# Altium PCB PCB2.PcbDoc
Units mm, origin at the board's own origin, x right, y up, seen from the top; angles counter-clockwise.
Board outline 51.56 x 61.72 mm, 2 copper layers (Top Layer, Bottom Layer); 23 components, 19 nets, 92 pads, 7 vias.
Unrouted connection lines stored in the file: 1.
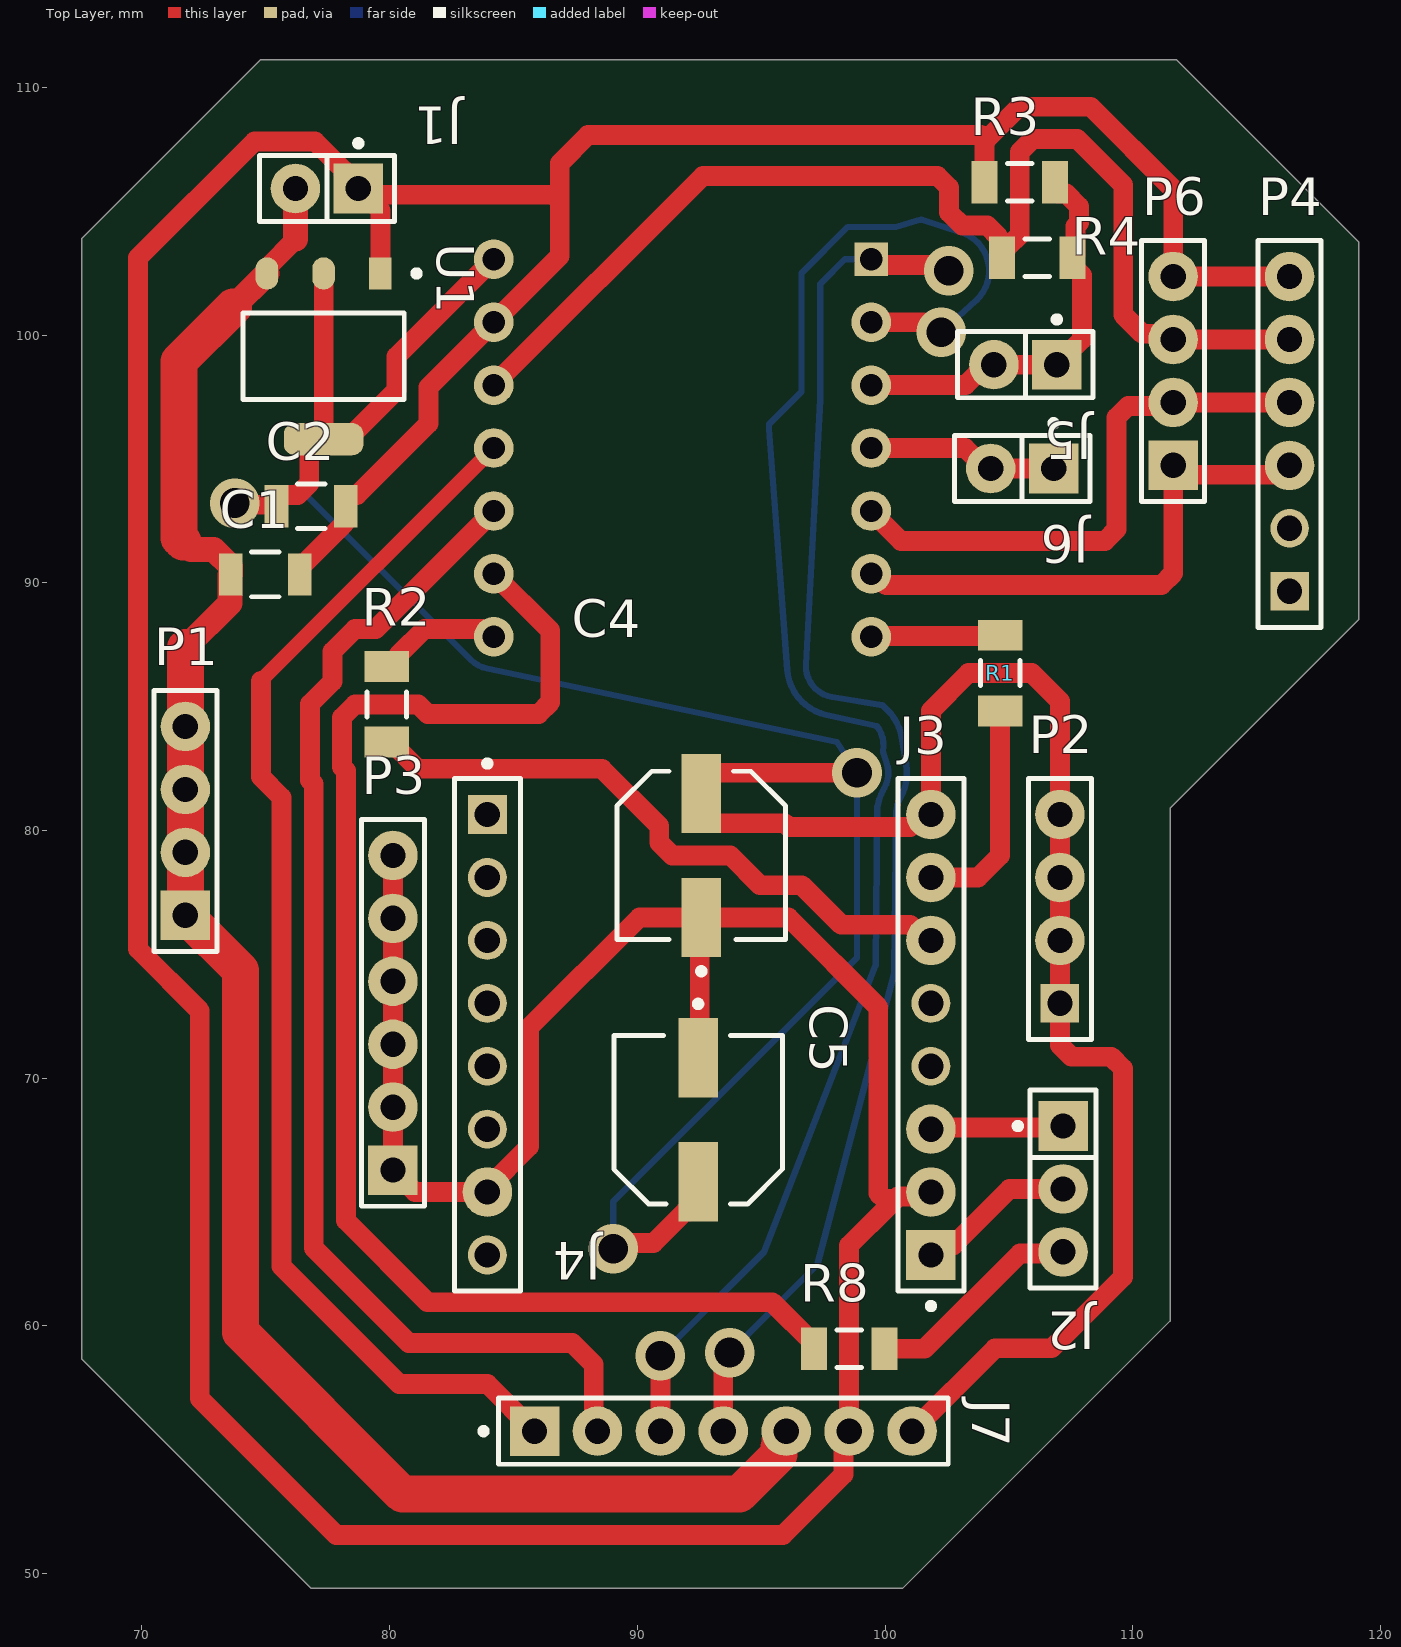
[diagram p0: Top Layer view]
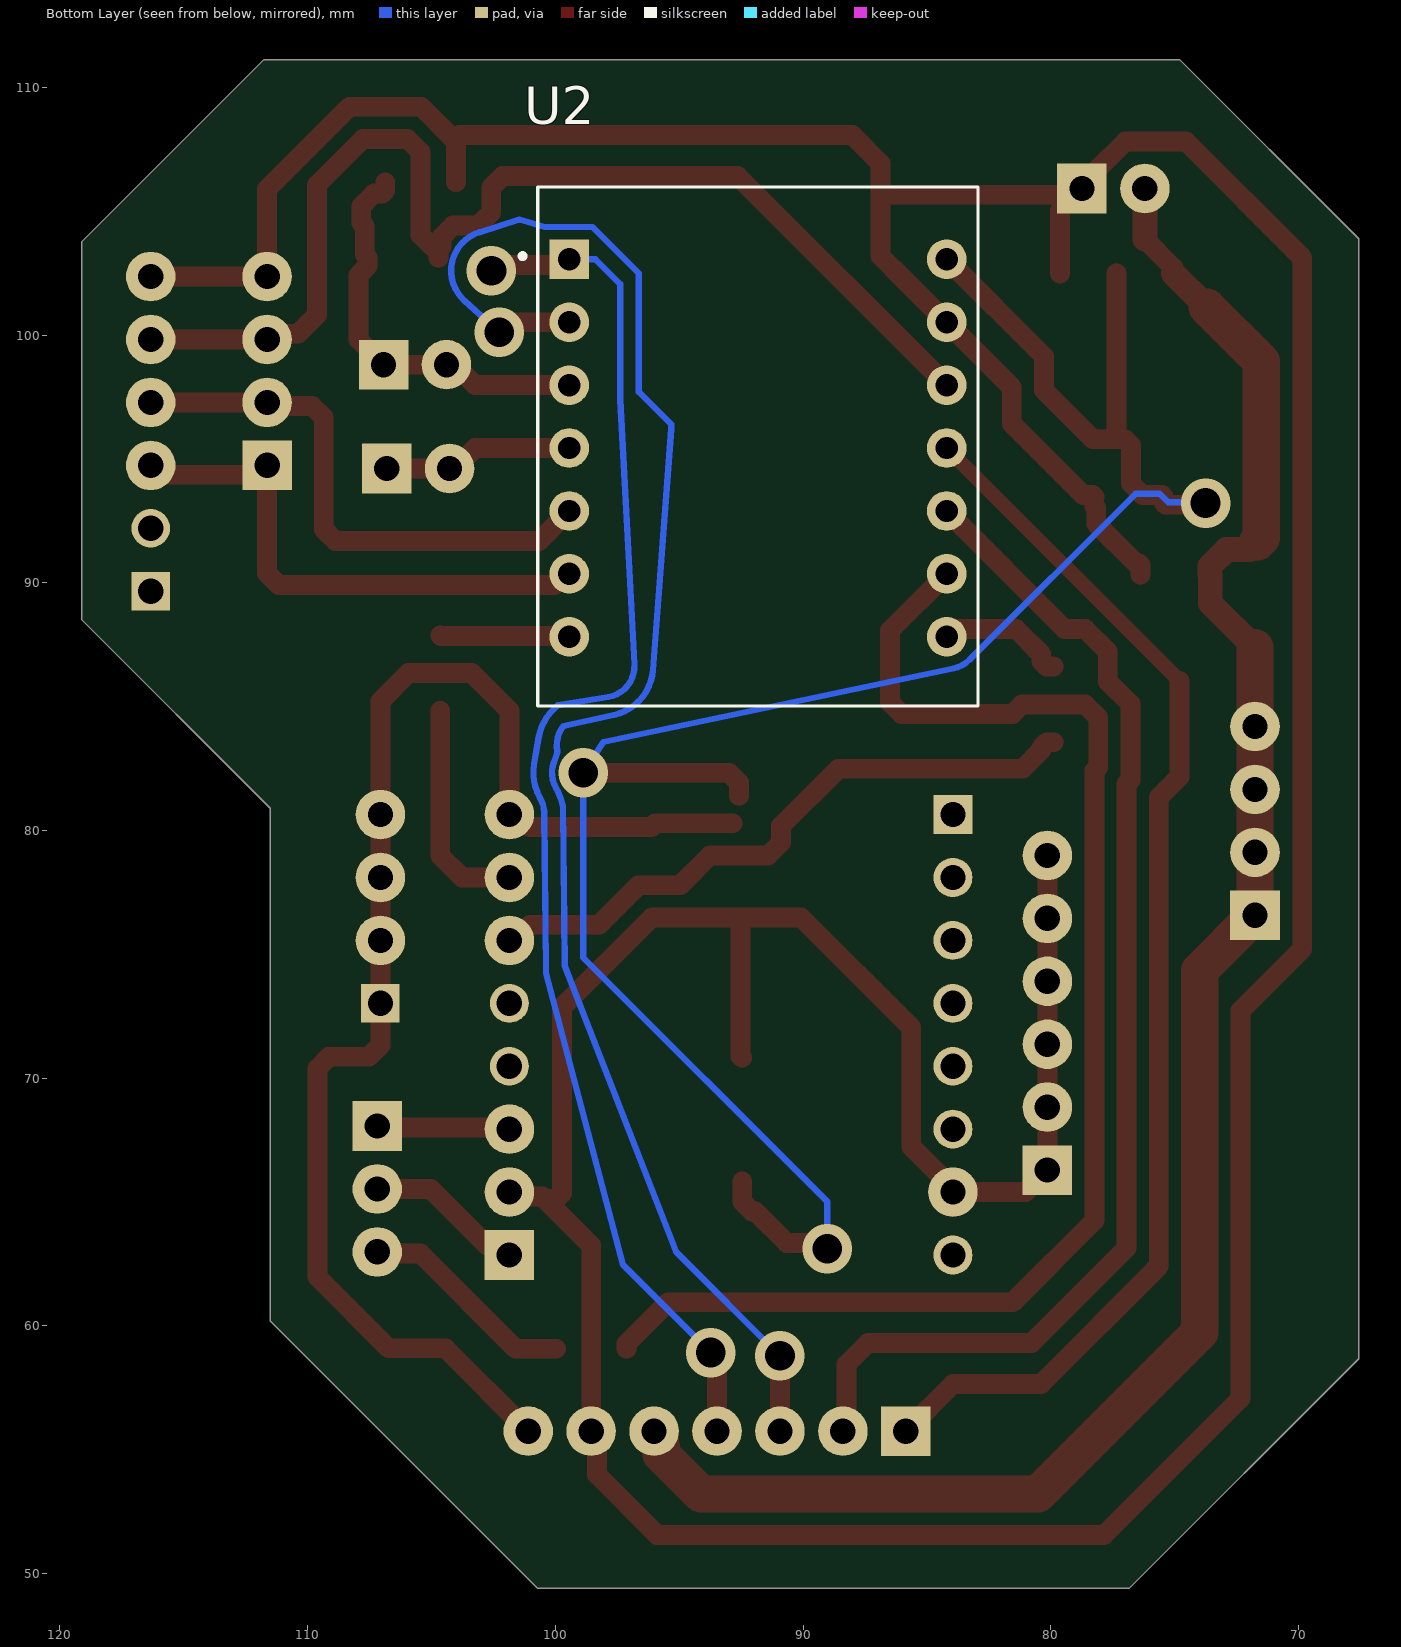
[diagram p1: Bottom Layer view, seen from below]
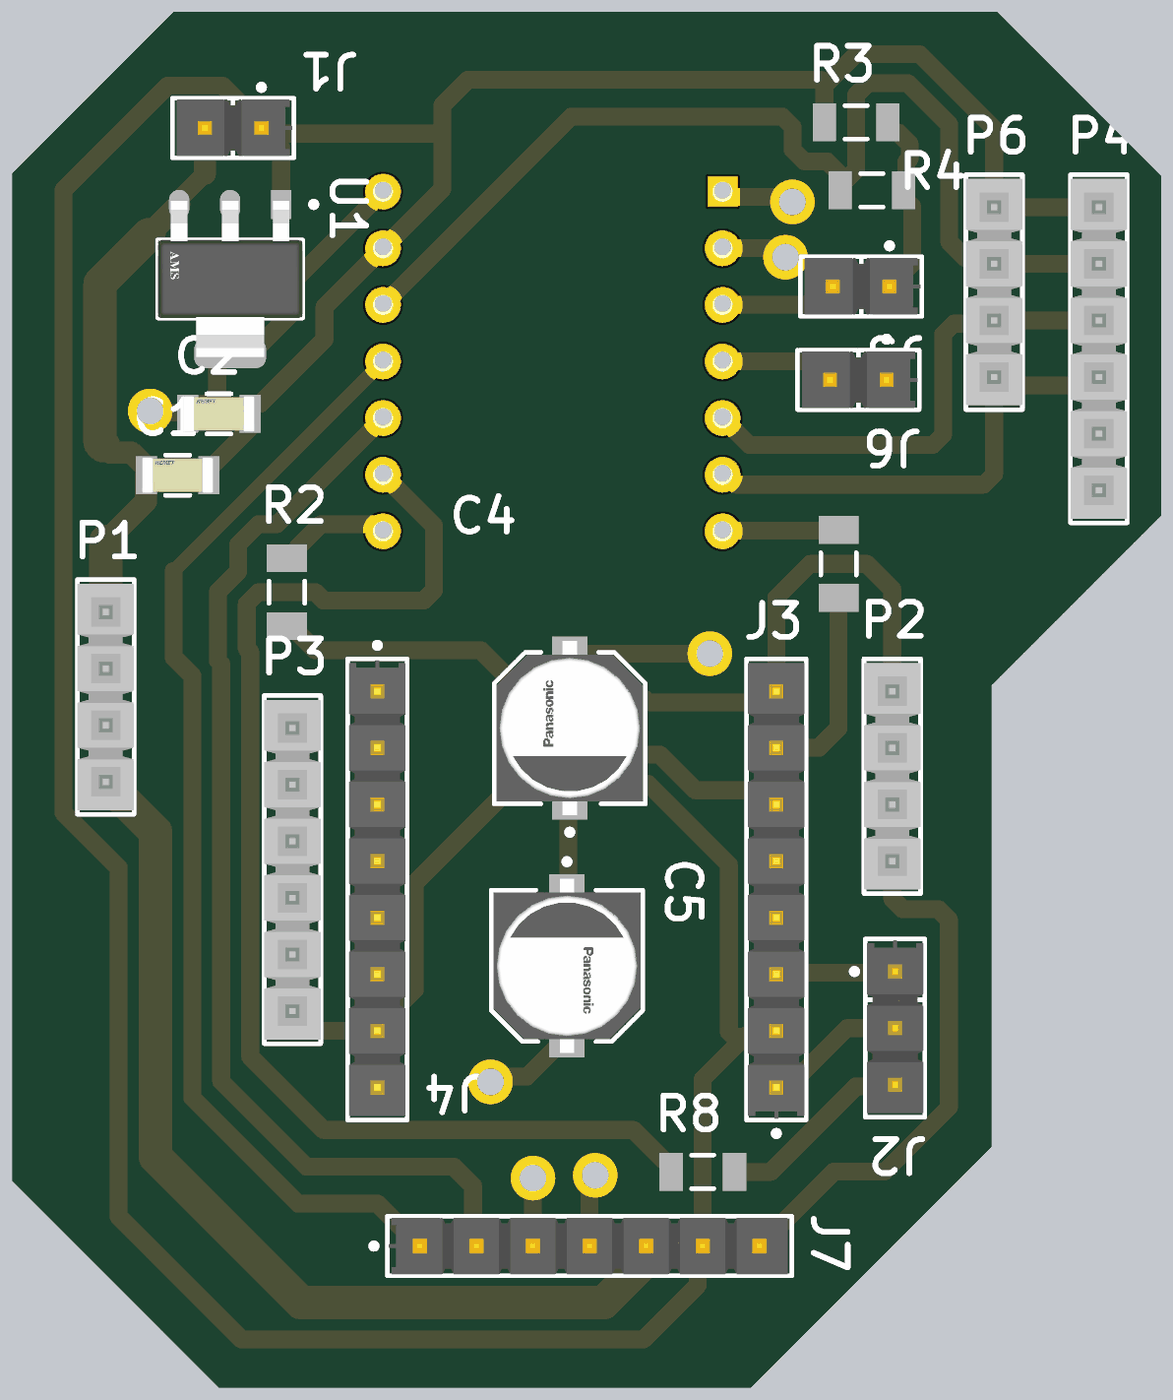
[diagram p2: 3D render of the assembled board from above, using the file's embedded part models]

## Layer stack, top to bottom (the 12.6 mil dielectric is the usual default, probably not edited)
Top Solder: solder mask 0.0102, Solder Resist, Dk 3.5
Top Layer: signal copper 0.0356
Dielectric 1: dielectric 0.32, FR-4, Dk 4.8
Bottom Layer: signal copper 0.0356
Bottom Solder: solder mask 0.0102, Solder Resist, Dk 3.5

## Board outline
67.564,58.674 76.835,49.403 100.711,49.403 111.506,60.198 111.506,80.899 119.126,88.519 119.126,103.759 111.76,111.125 74.803,111.125 67.564,103.886

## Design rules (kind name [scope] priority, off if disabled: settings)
Clearance [All] p1: gap=0.5 ignorepadtopadclearanceinfootprint=FALSE
PolygonConnect [All] p1: connectstyle=Relief reliefconductorwidth=0.254 reliefentries=4 polygonreliefangle="90 Angle" airgapwidth=0.254
RoutingVias [All] p1: holewidth=0.711 width=1.27 viastyle="Through Hole" minholewidth=0.711 minwidth=1.27 maxholewidth=0.711 maxwidth=1.27
SolderMaskExpansion [All] p1: expansion=0 istentingtop=FALSE
SupplyNets "Schematic Supply Nets_3" [InNet('+9')] p1: voltage=0.000
SupplyNets "Schematic Supply Nets_2" [InNet('GND')] p2: voltage=0.000
SupplyNets "Schematic Supply Nets_1" [InNet('+3.3')] p3: voltage=0.000
SupplyNets "Schematic Supply Nets" [InNet('VCC3.3')] p4: voltage=0.000
Width [All] p1: maxlimit=1.6 minlimit=0.254 preferedwidth=0.8 toplayer_minwidth=0.6 bottomlayer_maxwidth=0.254 bottomlayer_prefwidth=0.254 minimp=50.000000 maximp=50.000000 favimp=50.000000
30 further rules are at their usual default settings.

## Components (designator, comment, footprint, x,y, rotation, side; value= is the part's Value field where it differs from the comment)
C1 "C1206C153K5RAC" FP-C1206C-EB-MFG 74.983,90.338 r0 top value="15,000 pF"
C2 "C1206C153K5RAC" FP-C1206C-EB-MFG 76.835,93.091 r0 top value="15,000 pF"
C4 "EEEFPC221XAP" FP-FPD8-MFG 92.583,78.994 r90 top
C5 "EEEFPC221XAP" FP-FPD8-MFG 92.456,68.326 r270 top
J1 "BATERIA" FP-TSW-102-14-G-S-MFG 77.47,105.918 r180 top
J2 "TSW-103-14-G-S" FP-TSW-103-14-G-S-MFG 107.188,65.532 r270 top
J3 "TSW-108-08-G-S" FP-TSW-108-08-G-S-MFG#1 101.854,71.755 r90 top
J4 "TSW-108-08-G-S" FP-TSW-108-08-G-S-MFG#2 83.947,71.755 r270 top
J5 "TSW-102-14-G-S" FP-TSW-102-14-G-S-MFG 105.664,98.806 r180 top
J6 "TSW-102-14-G-S" FP-TSW-102-14-G-S-MFG 105.537,94.615 r180 top
J7 "TSW-107-07-G-S" FP-TSW-107-07-G-S-MFG 93.472,55.753 r0 top
P1 "TSW-104-08-G-S" SMTC-TSW-104-08-X-S#1 71.755,76.581 r90 top
P2 "TSW-104-08-G-S" SMTC-TSW-104-08-X-S#2 107.061,73.025 r90 top
P3 "TSW-106-17-L-S-LL" SMTC-TSW-106-17-X-S-LL#1 80.137,66.294 r90 top
P4 "TSW-106-17-L-S-LL" SMTC-TSW-106-17-X-S-LL#2 116.332,89.662 r90 top
P6 "TSW-104-08-G-S" SMTC-TSW-104-08-X-S#1 111.633,94.742 r90 top
R1 "RC1206FR-10750RL" RESC3116X65X40ML10T20 104.648,86.359 r270 top
R2 "RC1206FR-10750RL" RESC3116X65X40ML10T20 79.883,85.091 r270 top
R3 "RC1206FR-076R98L" RESC3116X65X40NL10T20 105.438,106.172 r0 top
R4 "RC1206FR-076R98L" RESC3116X65X40NL10T20 106.144,103.124 r0 top
R8 "RC1206FR-076R98L" RESC3116X65X40NL10T20 98.552,59.079 r0 top
U1 "ams1117" FP-ams1117-IPC_B 77.339,99.144 r270 top
U2 "XIAO_ESP32C3" MODULE_XIAO_ESP32C3 91.821,95.504 r180 bottom

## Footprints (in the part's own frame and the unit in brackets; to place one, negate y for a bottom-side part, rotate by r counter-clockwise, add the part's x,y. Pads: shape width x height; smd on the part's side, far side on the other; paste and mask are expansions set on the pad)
FP-ams1117-IPC_B [mm]
  rect 1.304x0.912 smd paste+0 mask+0: 1(-3.345,2.29)
  rrect100% 1.304x0.912 smd paste+0 mask+0: 2(-3.345,0) 3(-3.345,-2.29)
  rrect70% 1.304x3.222 smd paste+0 mask+0: 4(3.345,0)
  silkscreen extent -3.47,-3.25 1.75,3.88, body extent -4.25,-3.5 4.25,3.5, height 0.25
FP-C1206C-EB-MFG [mm]
  rect 0.95x1.7 smd paste+0 mask+0: 1(-1.4,0) 2(1.4,0)
  silkscreen extent -0.55,-0.9 0.55,0.9, body extent -2,-1 2,1, height 0.25
FP-FPD8-MFG [mm]
  rect 3.2x1.6 smd paste+0 mask+0: 1(-2.5,0) 2(2.5,0)
  silkscreen extent -4.8,-3.4 3.4,3.4, body extent -4.35,-3.65 4.35,3.65, height 0.25
FP-TSW-102-14-G-S-MFG [mm]
  rect 2x2 hole 1.02 paste-2539.97 mask+0: 1(-1.27,0)
  round 2 hole 1.02 paste-2539.97 mask+0: 2(1.27,0)
  silkscreen extent -2.73,-1.95 2.73,1.34, body extent -2.83,-1.44 2.83,1.44, height 0.25
FP-TSW-103-14-G-S-MFG [mm]
  rect 2x2 hole 1.02 paste-2539.97 mask+0: 1(-2.54,0)
  round 2 hole 1.02 paste-2539.97 mask+0: 2(0,0) 3(2.54,0)
  silkscreen extent -4,-1.95 4,1.34, body extent -4.1,-1.44 4.1,1.44, height 0.25
FP-TSW-107-07-G-S-MFG [mm]
  rect 2x2 hole 1.02 paste-2539.97 mask+0: 1(-7.62,0)
  round 2 hole 1.02 paste-2539.97 mask+0: 2(-5.08,0) 3(-2.54,0) 4(0,0) 5(2.54,0) 6(5.08,0) 7(7.62,0)
  silkscreen extent -9.8,-1.34 9.08,1.34, body extent -9.18,-1.44 9.18,1.44, height 0.25
FP-TSW-108-08-G-S-MFG#1 [mm]
  rect 2x2 hole 1.02 paste-2539.97 mask+0: 1(-8.89,0)
  round 2 hole 1.02 paste-2539.97 mask+0: 2(-6.35,0) 3(-3.81,0) 6(3.81,0) 7(6.35,0) 8(8.89,0)
  round 1.57 hole 1.02 paste-2539.97 mask+0: 4(-1.27,0) 5(1.27,0)
  silkscreen extent -11.07,-1.34 10.35,1.34, body extent -10.45,-1.44 10.45,1.44, height 0.25
FP-TSW-108-08-G-S-MFG#2 [mm]
  rect 1.57x1.57 hole 1.02 paste-2539.97 mask+0: 1(-8.89,0)
  round 1.57 hole 1.02 paste-2539.97 mask+0: 2(-6.35,0) 3(-3.81,0) 4(-1.27,0) 5(1.27,0) 6(3.81,0) 8(8.89,0)
  round 2 hole 1.02 paste-2539.97 mask+0: 7(6.35,0)
  silkscreen extent -11.07,-1.34 10.35,1.34, body extent -10.45,-1.44 10.45,1.44, height 0.25
MODULE_XIAO_ESP32C3 [mm]
  rect 1.6x1.6 / inner round 1.358 / far side rect 1.358x1.358 hole 0.9 mask+0.102: 1(-7.62,7.557)
  round 1.6 hole 0.9 mask+0.102: 2(-7.62,5.017) 3(-7.62,2.477) 4(-7.62,-0.063) 5(-7.62,-2.603) 6(-7.62,-5.143) 7(-7.62,-7.683) 8(7.62,-7.684) 9(7.62,-5.144) 10(7.62,-2.604) 11(7.62,-0.064) 12(7.62,2.476) 13(7.62,5.016) 14(7.62,7.556)
  silkscreen extent -9.6,-10.48 8.89,10.48, body extent -8.89,-10.48 8.89,11.99, height 4.21
RESC3116X65X40ML10T20 [mm] "Chip Resistor, 2-Leads, Body 3.10x1.60mm, IPC Low Density"
  rect 1.25x1.8 smd: 1(-1.525,0) 2(1.525,0)
  silkscreen extent -0.5,-0.8 0.5,0.8, body extent -1.6,-0.85 1.6,0.85, height 0.65
RESC3116X65X40NL10T20 [mm] "Chip Resistor, 2-Leads, Body 3.10x1.60mm, IPC Medium Density"
  rect 1.05x1.7 smd: 1(-1.425,0) 2(1.425,0)
  silkscreen extent -0.5,-0.75 0.5,0.75, body extent -1.6,-0.85 1.6,0.85, height 0.65
SMTC-TSW-104-08-X-S#1 [mm] ".025 SQ Post Terminal Strip Assembly, 1x4 Pins, Vertical, 2.54mm Pitch, Male"
  rect 2x2 hole 1.02: 1(0,0)
  round 2 hole 1.02: 2(2.54,0) 3(5.08,0) 4(7.62,0)
  silkscreen extent -1.46,-1.27 9.08,1.27, body extent -1.27,-1.27 8.89,1.27, height 8.38
SMTC-TSW-104-08-X-S#2 [mm] ".025 SQ Post Terminal Strip Assembly, 1x4 Pins, Vertical, 2.54mm Pitch, Male"
  rect 1.55x1.55 hole 1.02: 1(0,0)
  round 2 hole 1.02: 2(2.54,0) 3(5.08,0) 4(7.62,0)
  silkscreen extent -1.46,-1.27 9.08,1.27, body extent -1.27,-1.27 8.89,1.27, height 8.38
SMTC-TSW-106-17-X-S-LL#1 [mm] ".025 SQ Post Terminal Strip Assembly, 1x6 Pins, Vertical, 2.54mm Pitch, Male"
  rect 2x2 hole 1.02: 1(0,0)
  round 2 hole 1.02: 2(2.54,0) 3(5.08,0) 4(7.62,0) 5(10.16,0) 6(12.7,0)
  silkscreen extent -1.46,-1.27 14.16,1.27, body extent -1.27,-1.27 13.97,1.27, height 18.29
SMTC-TSW-106-17-X-S-LL#2 [mm] ".025 SQ Post Terminal Strip Assembly, 1x6 Pins, Vertical, 2.54mm Pitch, Male"
  rect 1.55x1.55 hole 1.02: 1(0,0)
  round 1.55 hole 1.02: 2(2.54,0)
  round 2 hole 1.02: 3(5.08,0) 4(7.62,0) 5(10.16,0) 6(12.7,0)
  silkscreen extent -1.46,-1.27 14.16,1.27, body extent -1.27,-1.27 13.97,1.27, height 18.29

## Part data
C1 C2: library part CMP-03020-027494-1, "C1206 15,000 pF X7R 10.00% 50 V", Capacitance="15,000 pF", Manufacturer=KEMET, Package=C1206C-EB, Temperature="-55°C to +150°C", Temperature Characteristic=X7R, Temperature Coefficient=15%, Temperature Range High=+150°C, Temperature Range Low=-55°C, Tolerance=0.1, Voltage Rating="50 V"
C4 C5: library part CMP-05427-002138-1, "CAP ALUM 220UF 20% 16V SMD", Capacitance=220uF, Case/Package=SMD/SMT, ESR (Equivalent Series Resistance)=160mR, Leakage Current=35.2uA, Max Operating Temperature=105°C, Min Operating Temperature=-55°C, Package Quantity=900, Ripple Current=600mA, Tolerance=20%, Voltage=16V
J1 J5 J6: library part CMP-02766-001740-1, "CONN HEADER VERT 2POS 2.54MM", Color=Black, Flammability Rating="UL94 V-0", Max Current Rating=7.6A, Max Operating Temperature=125°C, Max Voltage Rating (AC)=550V, Min Operating Temperature=-55°C, Package Quantity=1
J2: library part CMP-02766-001743-1, "CONN HEADER VERT 3POS 2.54MM", Color=Black, Flammability Rating="UL94 V-0", Max Current Rating=7.6A, Max Operating Temperature=125°C, Max Voltage Rating (AC)=550V, Min Operating Temperature=-55°C, Package Quantity=1
J3 J4: library part CMP-02766-000001-1, "CONN HEADER VERT 8POS 2.54MM", Manufacturer=Samtec, Temperature="-55°C to +125°C", Temperature Range High=+125°C, Temperature Range Low=-55°C
J7: library part CMP-02766-000065-1, "CONN HEADER VERT 7POS 2.54MM", Manufacturer=SAMTEC, Package=0, Temperature="-55°C to +125°C", Temperature Range High=+125°C, Temperature Range Low=-55°C
P1 P2 P6: library part CMP-1024-00357-1, "0.025\" SQ Post Header, Through-hole, Vertical, -55 to 125 degC, 2.54 mm Pitch, 4-Pin, Male, RoHS", Manufacturer=Samtec, Temperature Range="-55 to 125 degC"
P3 P4: library part CMP-1024-00394-1, "0.025\" SQ Post Header, Through-hole, Vertical, -55 to 125 degC, 2.54 mm Pitch, 6-Pin, Male, RoHS", Manufacturer=Samtec, Temperature Range="-55 to 125 degC"
R1 R2: library part CMP-2003-04964-1, Manufacturer=Yageo
R3 R4 R8: library part CMP-2003-03854-1, Manufacturer=Yageo
U1: library part CMP-209535-000002-1, "1A LOW DROPOUT VOLTAGE REGULATOR"
U2: "Dev.kit: evaluation; u.FL antenna,prototype board; XIAO; PIN: 2x7", Package=None

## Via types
v1: diameter 2, hole 1.2, Top Layer to Bottom Layer, 7 vias

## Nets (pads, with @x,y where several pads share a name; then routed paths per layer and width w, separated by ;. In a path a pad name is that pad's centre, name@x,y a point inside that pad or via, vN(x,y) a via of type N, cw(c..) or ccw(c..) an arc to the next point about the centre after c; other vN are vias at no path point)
+3.3: C2.1 C4.2 C5.2 J3.8 J7.7 P2.1 P2.2 P2.3 P2.4 U1.2 U1.4 U2.14 | length 143.6
  Top Layer w0.8: v1(73.75,93.218) 73.813,93.154 75.36,93.154 75.435,93.229 75.435,93.466 75.51,93.541 76.291,93.541 76.759,94.01 76.759,95.551 77.007,95.799 U1.4 ; U1.2 U1.4 ; U2.14 80.275,99.134 80.275,97.776 78.298,95.799 U1.4 ; v1(89.027,63.119) 89.257,63.349 90.654,63.349 91.931,64.626 92.056,64.626 92.456,65.026 C5.2 ; C4.2@92.583,81.407 C4.2 92.583,81.932 92.983,82.332 v1(98.87,82.332) ; C4.2@92.837,80.294 95.954,80.294 96.111,80.137 101.021,80.137 101.529,80.645 J3.8 101.854,84.838 103.375,86.359 105.921,86.359 107.061,85.219 P2.4 P2.3 P2.2 107.061,71.335 107.53,70.866 109.132,70.866 109.601,70.397 109.601,61.976 106.722,59.097 104.436,59.097 J7.7
  Bottom Layer w0.254: v1(73.75,93.218) 73.788,93.256 75.258,93.256 75.601,93.599 76.576,93.599 83.279,86.896 ccw(c84.201,87.82) 83.932,86.542 98.063,83.569 v1(98.87,82.332) 98.87,74.867 89.027,65.024 v1(89.027,63.119)
+9: C1.1 J1.2 J7.5 P1.1 P1.2 P1.3 P1.4 U1.3 | length 77.3
  Top Layer w0.8: U1.3 75.049,102.715 76.2,103.866
  Top Layer w1: 71.655,91.66 71.97,91.345 72.901,91.345 73.583,90.663 C1.1 73.558,90.313 73.558,89.179 71.755,87.376 ; 73.691,101.131 U1.3 ; 76.2,103.866 J1.2
  Top Layer w1.5: 71.655,91.66 71.5,91.815 71.5,98.94 73.691,101.131 ; P1.1 P1.2 P1.3 P1.4 71.755,87.376 ; P1.1@71.78,76.556 73.987,74.349 73.987,59.744 80.518,53.213 94.114,53.213 95.722,54.821 95.722,55.109 95.762,55.149 95.762,55.368 96.012,55.618 J7.5
BOTONAN: J5.1 J5.2 R3.2 R4.2 U2.3 | length 16.5
  Top Layer w0.8: U2.3 103.244,97.98 104.069,98.806 J5.1 107.95,99.822 107.95,102.418 107.569,102.799 R4.2 107.694,103.249 107.694,104.392 107.837,104.535 107.837,105.198 107.313,105.722 106.988,105.722 106.863,105.847 R3.2
BOTONDIG: J6.1 J6.2 U2.4 | length 7.7
  Top Layer w0.8: U2.4 103.233,95.441 104.059,94.615 J6.2 J6.1
EXTRA: J2.3 R8.1 R8.2 U2.9 | length 65.5
  Top Layer w0.8: U2.9 86.487,88.075 86.487,85.178 86.018,84.709 81.538,84.709 81.156,85.091 78.61,85.091 78.083,84.564 78.083,82.568 78.237,82.414 78.237,64.257 81.534,60.96 95.446,60.96 97.127,59.279 R8.1 ; R8.2 101.6,59.079 105.443,62.923 107.119,62.923 J2.3
GND: C1.2 C2.2 C4.1 C5.1 J1.1 J3.2 J4.7 J7.6 P3.1 P3.2 P3.3 P3.4 P3.5 P3.6 P4.6 P6.4 R3.1 U1.1 U2.13 | length 227
  Top Layer w0.8: C1.2 76.383,90.713 76.458,90.788 76.564,90.788 78.16,92.384 78.16,93.016 C2.2 ; C2.2@78.235,93.466 78.31,93.541 78.685,93.541 81.575,96.431 81.575,97.894 U2.13 85.933,102.253 86.868,103.188 86.868,105.664 86.868,106.934 88.011,108.077 103.869,108.077 104.013,107.933 R3.1 ; U1.1 79.629,102.503 79.629,105.029 J1.1@78.994,105.664 ; P3.6 P3.5 P3.4 P3.3 P3.2 P3.1 81.026,65.405 J4.7 83.947,65.562 85.632,67.247 85.632,72.043 90.083,76.494 C4.1 ; 86.868,105.41 86.614,105.664 J1.1@78.994,105.664 ; C5.1 92.519,70.89 92.519,76.43 C4.1 ; J3.2 101.67,65.221 100.527,65.221 100.44,65.134 ; 104.138,107.933 105.427,109.222 108.299,109.222 111.633,105.888 P6.4 P4.6 ; J1.1@78.994,105.664 78.14,106.518 78.14,106.665 76.987,107.818 74.544,107.818 69.85,103.124 69.85,75.213 72.337,72.726 72.337,57.076 77.85,51.563 95.886,51.563 98.322,53.999 98.322,55.523 J7.6 98.552,63.246 100.197,64.891 100.44,65.134 ; C4.1 96.099,76.494 99.727,72.866 99.727,65.361 99.954,65.134 100.44,65.134
MOTOR1A: J7.4 U2.1 | length 56.7
  Top Layer w0.8: J7.4 93.472,58.547 93.726,58.801 v1(93.726,58.928) ; U2.1 99.672,102.83 102.347,102.83 v1(102.577,102.6)
  Bottom Layer w0.254: v1(93.726,58.928) 97.266,62.468 100.374,74.239 100.378,74.413 100.442,80.66 cw(c101.854,80.645) 100.462,80.883 cw(c101.854,80.645) 100.626,81.342 ; U2.1 98.381,103.06 97.455,102.135 97.381,102.061 97.381,101.857 97.381,97.394 96.806,86.704 ccw(c98.067,86.637) 97.863,85.391 99.899,85.058 100.201,84.756 100.231,84.726 100.258,84.693 cw(c98.679,83.439) 100.666,83.781 100.856,82.674 cw(c98.87,82.332) 100.627,81.343
MOTOR1B: J7.3 U2.2 | length 68.1
  Top Layer w0.8: J7.3 v1(90.932,58.801) ; U2.2 101.541,100.52 101.942,100.119 v1(102.267,100.119)
  Bottom Layer w0.254: v1(90.932,58.801) 95.117,62.986 95.118,62.987 99.624,74.554 99.691,80.975 99.766,81.263 99.851,81.468 cw(c101.854,80.645) 99.969,81.712 ccw(c98.87,82.332) 100.062,82.746 99.935,83.111 cw(c100.175,83.194) 99.921,83.194 99.921,83.216 ccw(c98.679,83.439) 99.668,84.223 97.636,84.667 cw(c98.067,86.637) 96.056,86.483 95.316,96.215 95.316,96.396 96.627,97.707 96.627,102.491 98.502,104.366 100.274,104.366 100.437,104.366 101.304,104.629 101.458,104.661 103.068,104.151 cw(c102.577,102.6) 103.671,101.396 v1(102.267,100.119)
MOTOR2A: J7.2 U2.10 | length 49.4
  Top Layer w0.8: U2.10@84.19,92.89 79.441,88.141 78.61,88.141 77.697,87.227 77.697,86.016 76.783,85.102 76.783,82.03 76.937,81.876 76.937,63.144 80.772,59.309 87.376,59.309 88.245,58.44 88.245,55.9 J7.2
MOTOR2B: J7.1 U2.11 | length 50.2
  Top Layer w0.6: 74.803,86.042 U2.11@84.094,95.334
  Top Layer w0.8: 74.803,86.042 74.803,82.171 75.637,81.337 75.637,62.412 80.391,57.658 83.947,57.658 J7.1 ; U2.11@84.094,95.334 U2.11
NetJ3_6: J3.6 R2.2 | length 25.7
  Top Layer w0.8: R2.2 80.158,83.566 80.383,83.341 80.383,83.253 81.145,82.491 88.578,82.491 90.883,80.186 90.883,79.521 91.41,78.994 93.756,78.994 94.956,77.794 96.637,77.794 98.231,76.2 101.011,76.2 101.646,75.565 J3.6
NetJ3_7: J3.7 R1.2 | length 9
  Top Layer w0.8: J3.7 103.759,78.105 104.648,78.994 R1.2
RX: R2.1 U2.8 | length 5.2
  Top Layer w0.8: R2.1 80.158,86.616 80.383,86.841 80.383,87.116 81.405,88.138 83.733,88.138 84.05,87.82 U2.8
SCL: P4.3 P6.1 U2.6 | length 21.9
  Top Layer w0.8: U2.6 99.592,90.361 100.036,89.916 111.164,89.916 111.633,90.385 111.633,94.361 P6.1 112.014,94.361 115.626,94.361 116.007,94.742 P4.3
SDA: P4.4 P6.2 U2.5 | length 22.3
  Top Layer w0.8: U2.5 100.647,91.694 108.878,91.694 109.347,92.163 109.347,96.67 109.816,97.138 111.489,97.138 P6.2 P4.4
SPEAKER1: J2.2 J3.1 | length 6.4
  Top Layer w0.8: J3.1 102.239,63.25 102.747,63.25 105.029,65.532 J2.2
SPEAKER2: J2.1 J3.3 | length 5.4
  Top Layer w0.8: J3.3 101.917,68.008 107.124,68.008 J2.1
TX: R1.1 U2.7 | length 5.2
  Top Layer w0.8: U2.7 99.473,87.852 104.616,87.852 R1.1
VCC3.3: P4.5 P6.3 R4.1 U2.12 | length 48
  Top Layer w0.8: U2.12 92.647,106.426 102.119,106.426 102.588,105.957 102.588,104.949 103.115,104.422 104.125,104.422 104.594,103.953 104.594,103.574 104.719,103.574 R4.1 ; R4.1@104.969,103.574 105.438,104.043 105.438,107.395 105.965,107.922 107.761,107.922 109.617,106.066 109.617,100.822 110.387,100.052 111.403,100.052 P6.3 P4.5
pads on no net: J3.4 J3.5 J4.1 J4.2 J4.3 J4.4 J4.5 J4.6 J4.8 P4.1 P4.2

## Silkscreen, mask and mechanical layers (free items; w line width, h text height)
Mechanical 1:
  the board outline again, w2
